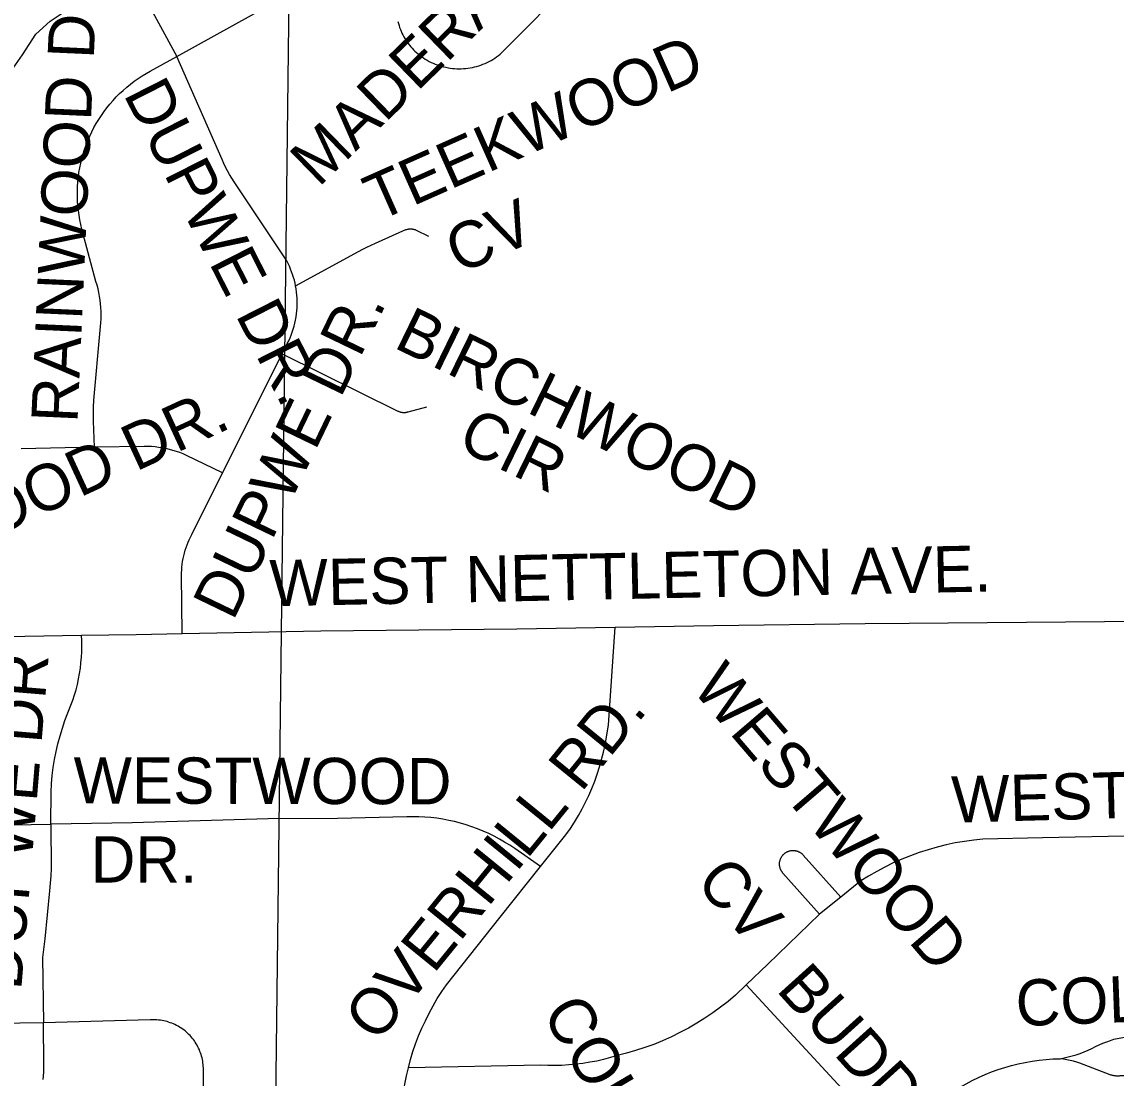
# Model space of a CAD drawing. Extents: x 1670563 to 1761545, y 515755 to 578944.
# Drawn here: x 1688082 to 1689856, y 545971 to 547684 of the extents above; entities that cross this region are included whole.
import ezdxf

# ---------------------------------------------------------------- set-up
doc = ezdxf.new("R2010")
doc.units = 0
for name, color, linetype in [('5_sectionlines', 7, 'Continuous'), ('SHP_LINE', 7, 'Continuous'), ('STREETCL', 7, 'Continuous'), ('STRNAMES', 7, 'Continuous')]:
    doc.layers.add(name, color=color, linetype=linetype)

msp = doc.modelspace()

# ---------------------------------------------------------------- linework, layer by layer
at = {"layer": '5_sectionlines'}
msp.add_lwpolyline([(1688479.9, 544764.2), (1688534.5, 549296.2), (1688506.7, 550235.5)], dxfattribs=at)
at = {"layer": 'SHP_LINE'}
msp.add_lwpolyline([(1687145, 546904), (1687348, 546911), (1687511, 546918), (1687775, 547008), (1687891, 547047), (1687949, 547077), (1688003, 547127), (1688029, 547166), (1688041, 547225), (1688047, 547295), (1688037, 547498), (1688036, 547539), (1688039, 547567), (1688064, 547603), (1688083, 547630), (1688105, 547664), (1688128, 547685), (1688154, 547702), (1688207, 547726), (1688245, 547746), (1688290, 547771), (1688407, 547834)], dxfattribs=at)
at = {"layer": 'STREETCL'}
for points in [[(1688224.1, 547828.7), (1688333.2, 547627.7)], [(1688333.2, 547627.7), (1688570.4, 547759.6), (1688573, 547761.1), (1688575.5, 547762.4), (1688578.1, 547763.7), (1688580.8, 547764.9), (1688583.5, 547765.9), (1688586.2, 547766.9), (1688589, 547767.8), (1688591.7, 547768.6), (1688594.6, 547769.3), (1688597.4, 547769.9), (1688600.2, 547770.4), (1688603.1, 547770.7), (1688606, 547771), (1688608.9, 547771.2), (1688687.8, 547770.5)], [(1688691.9, 547684.3), (1688692.7, 547681.1), (1688693.6, 547677.9), (1688694.6, 547674.7), (1688695.8, 547671.6), (1688697, 547668.6), (1688698.4, 547665.5), (1688699.8, 547662.5), (1688701.4, 547659.6), (1688703, 547656.7), (1688704.8, 547653.9), (1688706.6, 547651.2), (1688708.5, 547648.5), (1688710.6, 547645.8), (1688712.7, 547643.3), (1688714.9, 547640.8), (1688717.2, 547638.4), (1688719.5, 547636.1), (1688722, 547633.9), (1688724.5, 547631.7), (1688727.3, 547629.5), (1688730.2, 547627.3), (1688733.2, 547625.3), (1688736.2, 547623.3), (1688739.3, 547621.5), (1688742.5, 547619.7), (1688745.7, 547618.1), (1688749, 547616.6), (1688752.3, 547615.2), (1688755.7, 547613.9), (1688759.1, 547612.8), (1688762.5, 547611.7), (1688766, 547610.8), (1688769.5, 547610), (1688773.1, 547609.3), (1688776.6, 547608.7), (1688780.2, 547608.3), (1688783.8, 547608), (1688787.4, 547607.8), (1688791, 547607.7), (1688794.6, 547607.7), (1688798.2, 547607.9), (1688801.8, 547608.2), (1688805.4, 547608.6), (1688808.9, 547609.1), (1688812.5, 547609.8), (1688816, 547610.6), (1688819.5, 547611.5), (1688822.9, 547612.5), (1688826.4, 547613.7), (1688829.7, 547614.9), (1688833.1, 547616.3), (1688836.4, 547617.8), (1688839.6, 547619.4), (1688842.8, 547621.1), (1688845.9, 547622.9), (1688848.9, 547624.8), (1688851.9, 547626.8), (1688854.8, 547629), (1688857.7, 547631.2), (1688981.6, 547756)], [(1688199.7, 546994), (1688198.3, 547036.4), (1688198.1, 547047.7), (1688198.2, 547059), (1688198.7, 547070.2), (1688208.9, 547183.6), (1688209.7, 547189.7), (1688210.2, 547195.8), (1688210.5, 547202), (1688210.7, 547208.1), (1688210.6, 547214.2), (1688210.3, 547220.4), (1688209.7, 547226.5), (1688209, 547232.6), (1688208.1, 547238.6), (1688206.9, 547244.7), (1688205.6, 547250.7), (1688204, 547256.6), (1688202.3, 547262.5), (1688179.6, 547347.7), (1688177.8, 547355.2), (1688176.2, 547362.8), (1688174.9, 547370.4), (1688173.8, 547378), (1688173, 547385.7), (1688172.5, 547393.4), (1688172.2, 547401.1), (1688172.2, 547408.8), (1688172.4, 547416.5), (1688172.9, 547424.2), (1688173.7, 547431.9), (1688174.7, 547439.5), (1688176, 547447.1), (1688177.6, 547454.6), (1688179.4, 547462.1), (1688181.4, 547469.6), (1688183.7, 547476.9), (1688186.3, 547484.2), (1688189.1, 547491.4), (1688192.2, 547498.5), (1688195.5, 547505.4), (1688199, 547512.3), (1688202.8, 547519), (1688206.8, 547525.6), (1688211, 547532.1), (1688215.4, 547538.4), (1688220.1, 547544.5), (1688224.9, 547550.5), (1688230, 547556.3), (1688235.3, 547562), (1688240.7, 547567.4), (1688246.3, 547572.7), (1688252.1, 547577.8), (1688258.1, 547582.7), (1688264.2, 547587.3), (1688270.5, 547591.8), (1688277, 547596), (1688283.6, 547600), (1688290.3, 547603.8), (1688333.2, 547627.7)], [(1688526, 547255.6), (1688525, 547260.3), (1688523.9, 547264.9), (1688522.6, 547269.5), (1688521.1, 547274.1), (1688519.5, 547278.6), (1688517.8, 547283), (1688515.9, 547287.4), (1688513.9, 547291.8), (1688511.7, 547296), (1688426.2, 547424.6), (1688422.5, 547430.3), (1688419, 547436.1), (1688415.7, 547442), (1688412.5, 547448.1), (1688409.6, 547454.2), (1688406.9, 547460.4), (1688333.2, 547627.7)], [(1688526, 547255.6), (1688627.9, 547311.6), (1688634.7, 547315.2), (1688641.6, 547318.6), (1688648.6, 547321.9), (1688655.7, 547324.9), (1688704.7, 547346.8), (1688705.5, 547347.1), (1688706.3, 547347.3), (1688707.1, 547347.5), (1688708, 547347.6), (1688708.8, 547347.8), (1688709.6, 547347.9), (1688710.5, 547347.9), (1688711.3, 547348), (1688712.2, 547348), (1688713, 547348), (1688713.9, 547347.9), (1688714.7, 547347.9), (1688715.5, 547347.8), (1688716.4, 547347.6), (1688717.2, 547347.5), (1688718, 547347.3), (1688718.9, 547347.1), (1688719.7, 547346.8), (1688720.5, 547346.5), (1688721.3, 547346.2), (1688741.3, 547336.3)], [(1688504.4, 547145.7), (1688512.5, 547162), (1688514.8, 547166.6), (1688516.9, 547171.2), (1688518.8, 547175.9), (1688520.5, 547180.6), (1688522.1, 547185.4), (1688523.5, 547190.3), (1688524.8, 547195.2), (1688525.8, 547200.2), (1688526.7, 547205.2), (1688527.4, 547210.2), (1688528, 547215.2), (1688528.4, 547220.3), (1688528.5, 547225.4), (1688528.6, 547230.4), (1688528.4, 547235.5), (1688528.1, 547240.6), (1688527.5, 547245.6), (1688526.8, 547250.6), (1688526, 547255.6)], [(1688407.6, 546952.6), (1688504.4, 547145.7)], [(1688504.4, 547145.7), (1688691.9, 547052.7), (1688692.6, 547052.4), (1688693.3, 547052.1), (1688694, 547051.8), (1688694.7, 547051.5), (1688695.5, 547051.3), (1688696.2, 547051.1), (1688696.9, 547050.9), (1688697.7, 547050.8), (1688698.4, 547050.7), (1688699.2, 547050.6), (1688699.9, 547050.5), (1688700.7, 547050.4), (1688701.5, 547050.4), (1688702.2, 547050.4), (1688703, 547050.5), (1688703.8, 547050.5), (1688704.5, 547050.6), (1688705.3, 547050.7), (1688706, 547050.8), (1688706.8, 547051), (1688707.5, 547051.2), (1688708.2, 547051.4), (1688738.6, 547059.3)], [(1688407.6, 546952.6), (1688349.2, 546980.9), (1688343.7, 546983.2), (1688338.2, 546985.3), (1688332.7, 546987.2), (1688327, 546988.9), (1688321.3, 546990.4), (1688315.6, 546991.8), (1688309.8, 546992.9), (1688303.9, 546993.8), (1688298.1, 546994.6), (1688292.2, 546995.1), (1688286.3, 546995.4), (1688280.4, 546995.5), (1688199.7, 546994)], [(1688199.7, 546994), (1688080.8, 546991.7)], [(1688341.9, 546692.1), (1688341.1, 546785.9), (1688341.1, 546790.6), (1688341.3, 546795.2), (1688341.7, 546799.8), (1688342.2, 546804.4), (1688342.8, 546808.9), (1688343.6, 546813.5), (1688344.6, 546818), (1688345.7, 546822.4), (1688347, 546826.9), (1688348.4, 546831.3), (1688350, 546835.6), (1688351.7, 546839.9), (1688353.6, 546844.1), (1688355.6, 546848.3), (1688357.8, 546852.3), (1688407.6, 546952.6)], [(1689449.2, 546708.1), (1689520.7, 546709), (1689837.2, 546711.4), (1690012.9, 546714.3)], [(1688341.9, 546692.1), (1688566.9, 546696.6), (1688884.7, 546699.4), (1689044, 546702.2)], [(1688923.1, 546314), (1688964.3, 546365.7), (1688971.4, 546375.8), (1688978.1, 546386.1), (1688984.5, 546396.7), (1688990.5, 546407.5), (1688996.1, 546418.4), (1689001.4, 546429.6), (1689006.3, 546440.9), (1689010.9, 546452.4), (1689015, 546464), (1689018.8, 546475.8), (1689022.1, 546487.6), (1689025.1, 546499.6), (1689027.7, 546511.7), (1689033.1, 546543.4), (1689044, 546702.2)], [(1689044, 546702.2), (1689203.7, 546705), (1689449.2, 546708.1)], [(1687700.7, 546683.1), (1687963.7, 546685.4), (1688178.7, 546689.1)], [(1688129, 546382.8), (1688129.4, 546435.3), (1688130.2, 546448.5), (1688131.4, 546461.6), (1688133.1, 546474.6), (1688135.2, 546487.6), (1688137.7, 546500.5), (1688140.6, 546513.3), (1688144, 546526.1), (1688147.8, 546538.6), (1688152, 546551.1), (1688156.6, 546563.4), (1688161.7, 546575.6), (1688164.7, 546583.9), (1688167.5, 546592.4), (1688170, 546600.9), (1688172.2, 546609.6), (1688174.1, 546618.3), (1688175.7, 546627), (1688177, 546635.8), (1688178, 546644.6), (1688178.8, 546653.5), (1688179.2, 546662.4), (1688179.3, 546671.3), (1688179.2, 546680.2), (1688178.7, 546689.1)], [(1688178.7, 546689.1), (1688267.5, 546690.6), (1688341.9, 546692.1)], [(1688923.1, 546314), (1688881.3, 546343.2), (1688873.2, 546348.7), (1688864.9, 546353.8), (1688856.4, 546358.7), (1688847.8, 546363.3), (1688839, 546367.6), (1688830.1, 546371.6), (1688821.1, 546375.3), (1688811.9, 546378.7), (1688802.6, 546381.8), (1688793.2, 546384.6), (1688783.8, 546387), (1688774.2, 546389.1), (1688764.6, 546390.9), (1688755, 546392.4), (1688745.2, 546393.5), (1688735.5, 546394.3), (1688725.7, 546394.8), (1688716, 546394.9), (1688706.2, 546394.7), (1688593.9, 546391.9), (1688481.7, 546391.5), (1688261, 546385), (1688129, 546382.8)], [(1687711.9, 546376), (1688129, 546382.8)], [(1688129, 546382.8), (1688129.8, 546311.1), (1688129.3, 546299), (1688128.3, 546287), (1688126.9, 546275), (1688119.3, 546197.1), (1688115.8, 546166.9), (1688117, 546060.9)], [(1690281.9, 546369.9), (1690037.9, 546366.9), (1689896.5, 546364), (1689737.1, 546361), (1689640.4, 546358.7), (1689625.4, 546357.1), (1689610.4, 546355), (1689595.5, 546352.4), (1689580.7, 546349.3), (1689566, 546345.7), (1689551.5, 546341.5), (1689537.1, 546336.9), (1689522.9, 546331.7), (1689508.9, 546326.1), (1689495, 546320), (1689481.4, 546313.4), (1689468.1, 546306.3), (1689455, 546298.8), (1689442.1, 546290.8), (1689409.8, 546264.6)], [(1689375.5, 546236.9), (1689316.1, 546303.7), (1689315.6, 546304.2), (1689315.1, 546304.8), (1689314.6, 546305.5), (1689314.2, 546306.1), (1689313.8, 546306.7), (1689313.4, 546307.4), (1689313, 546308.1), (1689312.7, 546308.7), (1689312.3, 546309.4), (1689312, 546310.2), (1689311.8, 546310.9), (1689311.5, 546311.6), (1689311.3, 546312.3), (1689311.1, 546313.1), (1689310.9, 546313.8), (1689310.8, 546314.6), (1689310.7, 546315.3), (1689310.6, 546316.1), (1689310.5, 546316.9), (1689310.5, 546317.6), (1689310.5, 546318.4), (1689310.5, 546319.2), (1689310.6, 546319.9), (1689310.6, 546320.7), (1689310.7, 546321.5), (1689310.8, 546322.2), (1689311, 546323), (1689311.2, 546323.7), (1689311.4, 546324.5), (1689311.6, 546325.2), (1689311.9, 546325.9), (1689312.1, 546326.6), (1689312.4, 546327.3), (1689312.8, 546328), (1689313.1, 546328.7), (1689313.5, 546329.4), (1689313.9, 546330), (1689314.3, 546330.7), (1689314.8, 546331.3), (1689315.2, 546331.9), (1689315.7, 546332.5), (1689316.2, 546333.1), (1689316.7, 546333.7), (1689317.3, 546334.2), (1689317.9, 546334.7), (1689318.4, 546335.2), (1689319, 546335.7), (1689319.7, 546336.2), (1689320.3, 546336.6), (1689320.9, 546337), (1689321.6, 546337.4), (1689322.3, 546337.8), (1689323, 546338.1), (1689323.6, 546338.4), (1689324.4, 546338.7), (1689325.1, 546339), (1689325.8, 546339.2), (1689326.5, 546339.5), (1689327.3, 546339.7), (1689328, 546339.8), (1689328.8, 546340), (1689329.5, 546340.1), (1689330.3, 546340.2), (1689331.1, 546340.2), (1689331.8, 546340.3), (1689332.6, 546340.3), (1689333.4, 546340.3), (1689334.1, 546340.2), (1689334.9, 546340.2), (1689335.7, 546340.1), (1689336.4, 546339.9), (1689337.2, 546339.8), (1689337.9, 546339.6), (1689338.7, 546339.4), (1689339.4, 546339.2), (1689340.1, 546338.9), (1689340.8, 546338.6), (1689341.5, 546338.3), (1689342.2, 546338), (1689342.9, 546337.7), (1689343.6, 546337.3), (1689344.2, 546336.9), (1689344.9, 546336.5), (1689345.5, 546336), (1689346.1, 546335.5), (1689346.7, 546335.1), (1689347.3, 546334.6), (1689347.9, 546334), (1689348.4, 546333.5), (1689348.9, 546332.9), (1689409.8, 546264.6)], [(1688708.8, 545988.1), (1688712.3, 546001.2), (1688716.2, 546014.1), (1688720.6, 546026.9), (1688725.4, 546039.6), (1688730.7, 546052), (1688736.3, 546064.3), (1688742.4, 546076.4), (1688748.9, 546088.3), (1688755.7, 546100), (1688763, 546111.4), (1688770.7, 546122.5), (1688857.7, 546232), (1688923.1, 546314)], [(1689409.8, 546264.6), (1689375.5, 546236.9)], [(1689375.5, 546236.9), (1689291.6, 546155.8), (1689256.5, 546122.2)], [(1689256.5, 546122.2), (1689239.1, 546105.6), (1689227.2, 546095.6), (1689214.9, 546086), (1689202.3, 546076.9), (1689189.5, 546068.2), (1689176.3, 546060), (1689162.8, 546052.3), (1689149.1, 546045), (1689135.2, 546038.1), (1689121, 546031.8), (1689106.6, 546025.9), (1689092, 546020.6), (1689077.2, 546015.8), (1689062.3, 546011.4), (1689047.2, 546007.6), (1689036.3, 546004.4), (1689025.3, 546001.5), (1689014.1, 545998.9), (1689002.9, 545996.8), (1688991.6, 545995), (1688980.3, 545993.6), (1688968.9, 545992.5), (1688957.5, 545991.8), (1688946.1, 545991.5), (1688934.7, 545991.6), (1688923.3, 545992), (1688708.8, 545988.1)], [(1689256.5, 546122.2), (1689495.4, 545863.7)], [(1688117, 546060.9), (1688002.3, 546059.3), (1687824.9, 546058.5)], [(1688116.9, 545968.9), (1688117.5, 545981), (1688117.7, 545993.2), (1688117, 546060.9)], [(1688368.7, 545128.9), (1688376.4, 545982.1), (1688376.5, 545984.8), (1688376.4, 545987.6), (1688376.3, 545990.3), (1688376.1, 545993.1), (1688375.8, 545995.8), (1688375.3, 545998.6), (1688374.8, 546001.3), (1688374.2, 546004), (1688373.6, 546006.7), (1688372.8, 546009.3), (1688371.9, 546011.9), (1688370.9, 546014.5), (1688369.9, 546017.1), (1688368.7, 546019.6), (1688367.5, 546022.1), (1688366.2, 546024.5), (1688364.8, 546026.9), (1688363.3, 546029.2), (1688361.8, 546031.5), (1688360.2, 546033.7), (1688358.5, 546035.9), (1688356.7, 546038), (1688354.8, 546040.1), (1688352.9, 546042.1), (1688350.9, 546044), (1688348.9, 546045.8), (1688346.8, 546047.6), (1688344.6, 546049.3), (1688342.3, 546051), (1688340.1, 546052.5), (1688337.7, 546054), (1688335.3, 546055.4), (1688332.9, 546056.7), (1688330.4, 546057.9), (1688327.9, 546059), (1688325.4, 546060.1), (1688322.8, 546061), (1688320.1, 546061.9), (1688317.5, 546062.7), (1688314.8, 546063.4), (1688312.1, 546064), (1688309.4, 546064.5), (1688306.7, 546064.9), (1688303.9, 546065.2), (1688301.2, 546065.4), (1688298.4, 546065.6), (1688295.6, 546065.6), (1688292.9, 546065.5), (1688290.1, 546065.4), (1688117, 546060.9)], [(1689765.3, 546002.6), (1689771.9, 546003.9), (1689778.6, 546005.4), (1689785.1, 546007.1), (1689791.7, 546009.1), (1689798.1, 546011.3), (1689804.5, 546013.7), (1689810.7, 546016.3), (1689816.9, 546019.2), (1689822.8, 546022.2), (1689828.8, 546025), (1689834.9, 546027.6), (1689841, 546030), (1689847.2, 546032.3), (1689850, 546033.3), (1689852.7, 546034.1), (1689855.5, 546034.9), (1689858.4, 546035.6), (1689861.2, 546036.2), (1689864.1, 546036.7), (1689867, 546037.1), (1689869.9, 546037.4), (1689872.8, 546037.6), (1690241.3, 546040.9)], [(1689495.4, 545863.7), (1689548.6, 545915.8), (1689557.1, 545923.3), (1689565.8, 545930.6), (1689574.8, 545937.5), (1689584.1, 545944.1), (1689593.5, 545950.4), (1689603.2, 545956.4), (1689613, 545962.1), (1689623.1, 545967.3), (1689633.3, 545972.3), (1689643.7, 545976.9), (1689654.3, 545981.1), (1689664.9, 545985), (1689675.8, 545988.5), (1689686.7, 545991.6), (1689697.7, 545994.3), (1689708.8, 545996.7), (1689720, 545998.6), (1689731.3, 546000.2), (1689742.6, 546001.4), (1689753.9, 546002.2), (1689765.3, 546002.6)], [(1690228.1, 545977.7), (1689873.4, 545974.6), (1689862.2, 545974.6), (1689861, 545974.5), (1689859.8, 545974.4), (1689858.6, 545974.4), (1689857.4, 545974.5), (1689856.2, 545974.5), (1689855, 545974.6), (1689853.8, 545974.8), (1689852.6, 545975), (1689851.4, 545975.3), (1689850.3, 545975.5), (1689849.1, 545975.9), (1689847.9, 545976.2), (1689846.8, 545976.6), (1689797.5, 545995.5), (1689792.3, 545997.2), (1689786.9, 545998.6), (1689781.6, 545999.9), (1689776.2, 546001), (1689770.7, 546001.9), (1689765.3, 546002.6)], [(1688697.2, 545478.1), (1688696.6, 545655.3), (1688698.7, 545853.5), (1688697.6, 545867.1), (1688697, 545880.6), (1688696.9, 545894.2), (1688697.2, 545907.7), (1688698, 545921.2), (1688699.3, 545934.7), (1688701, 545948.2), (1688703.1, 545961.6), (1688705.7, 545974.9), (1688708.8, 545988.1)]]:
    msp.add_lwpolyline(points, dxfattribs=at)

# ---------------------------------------------------------------- texts
at = {"layer": 'STRNAMES'}
for s, rotation, p in [('MADERA DR', 44.2113, (1688563.2, 547414.4)), ('RAINWOOD DR', 87.4344, (1688172.2, 547032.8)), ('TEEKWOOD', 23.9373, (1688659.3, 547359.4)), ('DUPWE DR.', 296.9373, (1688246.1, 547566.7)), (' CV', 23.9373, (1688765.7, 547262.8)), ('DUPWE DR.', 64.2599, (1688424.5, 546710.9)), ('BIRCHWOOD', 334.0316, (1688683.1, 547156.5)), ('CENWOOD DR.', 24.7818, (1687755.9, 546718.2)), (' CIR', 334.0316, (1688760.3, 547005.8)), ('WEST NETTLETON AVE.', 1.1877, (1688484.6, 546736)), ('DUPWE DR', 85.298, (1688081, 546112.6)), ('WESTWOOD', 310.6297, (1689166.3, 546603)), ('OVERHILL RD.', 50.8683, (1688658.3, 546026.7)), ('WESTWOOD', 359.8584, (1688165.8, 546416.5)), ('WESTWOOD DR.', 1.5511, (1689590.3, 546385.2)), (' DR.', 359.8584, (1688165.8, 546288.4)), ('CV', 310.6297, (1689172.5, 546288.6)), ('BUDDY ST.', 312.057, (1689303.6, 546113.8)), ('COLLEGE ', 2.1804, (1689694.8, 546055.2)), ('COLLEGE', 300.3979, (1688924.4, 546077))]:
    msp.add_text(s, height=75, rotation=rotation, dxfattribs=at).set_placement(p)

doc.saveas('drawing.dxf')
